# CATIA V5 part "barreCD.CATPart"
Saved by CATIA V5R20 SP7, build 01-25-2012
Part number: barreCD
Publications: "pivot_CD_CE", "pivot_CD_base", "Plan_Ref"
Bounding box of the stored display mesh (mm): x -15 to 23, y 644.836 to 717.216, z 67.722 to 277.801
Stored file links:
  G:\IAO\apres\barreCD.CATPart
  G:\IAO\apres\psedsuay.CATProduct
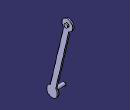
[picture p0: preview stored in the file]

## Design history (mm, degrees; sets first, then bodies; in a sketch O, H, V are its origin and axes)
External parameters (linked from other documents)
  External.Longueur_AB = 100 mm
  External.Diametre = 30 mm
  External.Largeur = 15 mm
  External.Epaisseur = 4 mm
  External.Diametre_pivot = 10 mm
Set1
  Point1 "Point_C": linked copy from another document
  Point2 "Point_D": linked copy from another document
  Plane1 "Plan_Ref": linked copy from another document
Set2 "skelette"
  Line1 "Barre_CD": type PtPt, FirstPoint Point1, SecondPoint Point2
  Line2 "pivot_CD_CE": type Normal, RefPoint Point1, RefSkin Plane1, Start -20, End 20
  Line3 "pivot_CD_base": type Normal, RefPoint Point2, RefSkin Plane1, Start -20, End 20
Set3 "piece"
  Plane2: type OffsetPt, RefPlane yz-plane, RefPoint Point2
  Plane3: type Offset, RefPlane Plane2, Offset 15 {= 0.15*External.Longueur_AB}
  Sketch1 on Plane3, origin (15, 0, 0), H (0, 1, 0), V (0, 0, 1)
    arc A1 centre (659.8349, 82.7215) radius 15 from (655.5104, 97.0846) to (670.1115, 93.6482) ccw
    arc A2 centre (702.2166, 262.8015) radius 15 from (706.5412, 248.4384) to (691.9401, 251.8747) ccw
    construction line L1 (659.8349, 82.7215) -> (702.2166, 262.8015)
    line L2 (670.1115, 93.6482) -> (706.5412, 248.4384)
    line L3 (655.5104, 97.0846) -> (691.9401, 251.8747)
    reference projected point E1 (702.2166, 262.8015) from Line2
    reference projected point E2 (659.8349, 82.7215) from Line3
    radius A2 = 15 {= External.Diametre /2}
    radius A1 = 15 {= External.Diametre /2}
    distance L2 L3 = 15 {= External.Largeur}
    parallelism: L2 L1, L3 L1
    symmetry: L2 L3 L1
    concentricity: A2 E1, A1 E2
  Sketch2 on Plane3, origin (15, 0, 0), H (0, 1, 0), V (0, 0, 1)
    circle A1 centre (659.8349, 82.7215) radius 5
    reference projected point E1 (659.8349, 82.7215) from Line3
    radius A1 = 5 {= External.Diametre_pivot /2}
    concentricity: A1 E1
  Plane4: type Offset, RefPlane Plane3, Offset 4 {= External.Epaisseur}
  Sketch3 on Plane4, origin (19, 0, 0), H (0, 1, 0), V (0, 0, 1)
    circle A1 centre (702.2166, 262.8015) radius 5
    reference projected point E1 (702.2166, 262.8015) from Line2
    radius A1 = 5 {= External.Diametre_pivot /2}
    concentricity: A1 E1
Body1 (main body)
  Pad1: profile Sketch1, direction (1, 0, 0), length 4 {= External.Epaisseur}
  Pad2: profile Sketch2, direction (-1, 0, 0), length 30 {= 0.3*External.Longueur_AB}
  Pad3: profile Sketch3, direction (1, 0, 0), length 4 {= External.Epaisseur}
